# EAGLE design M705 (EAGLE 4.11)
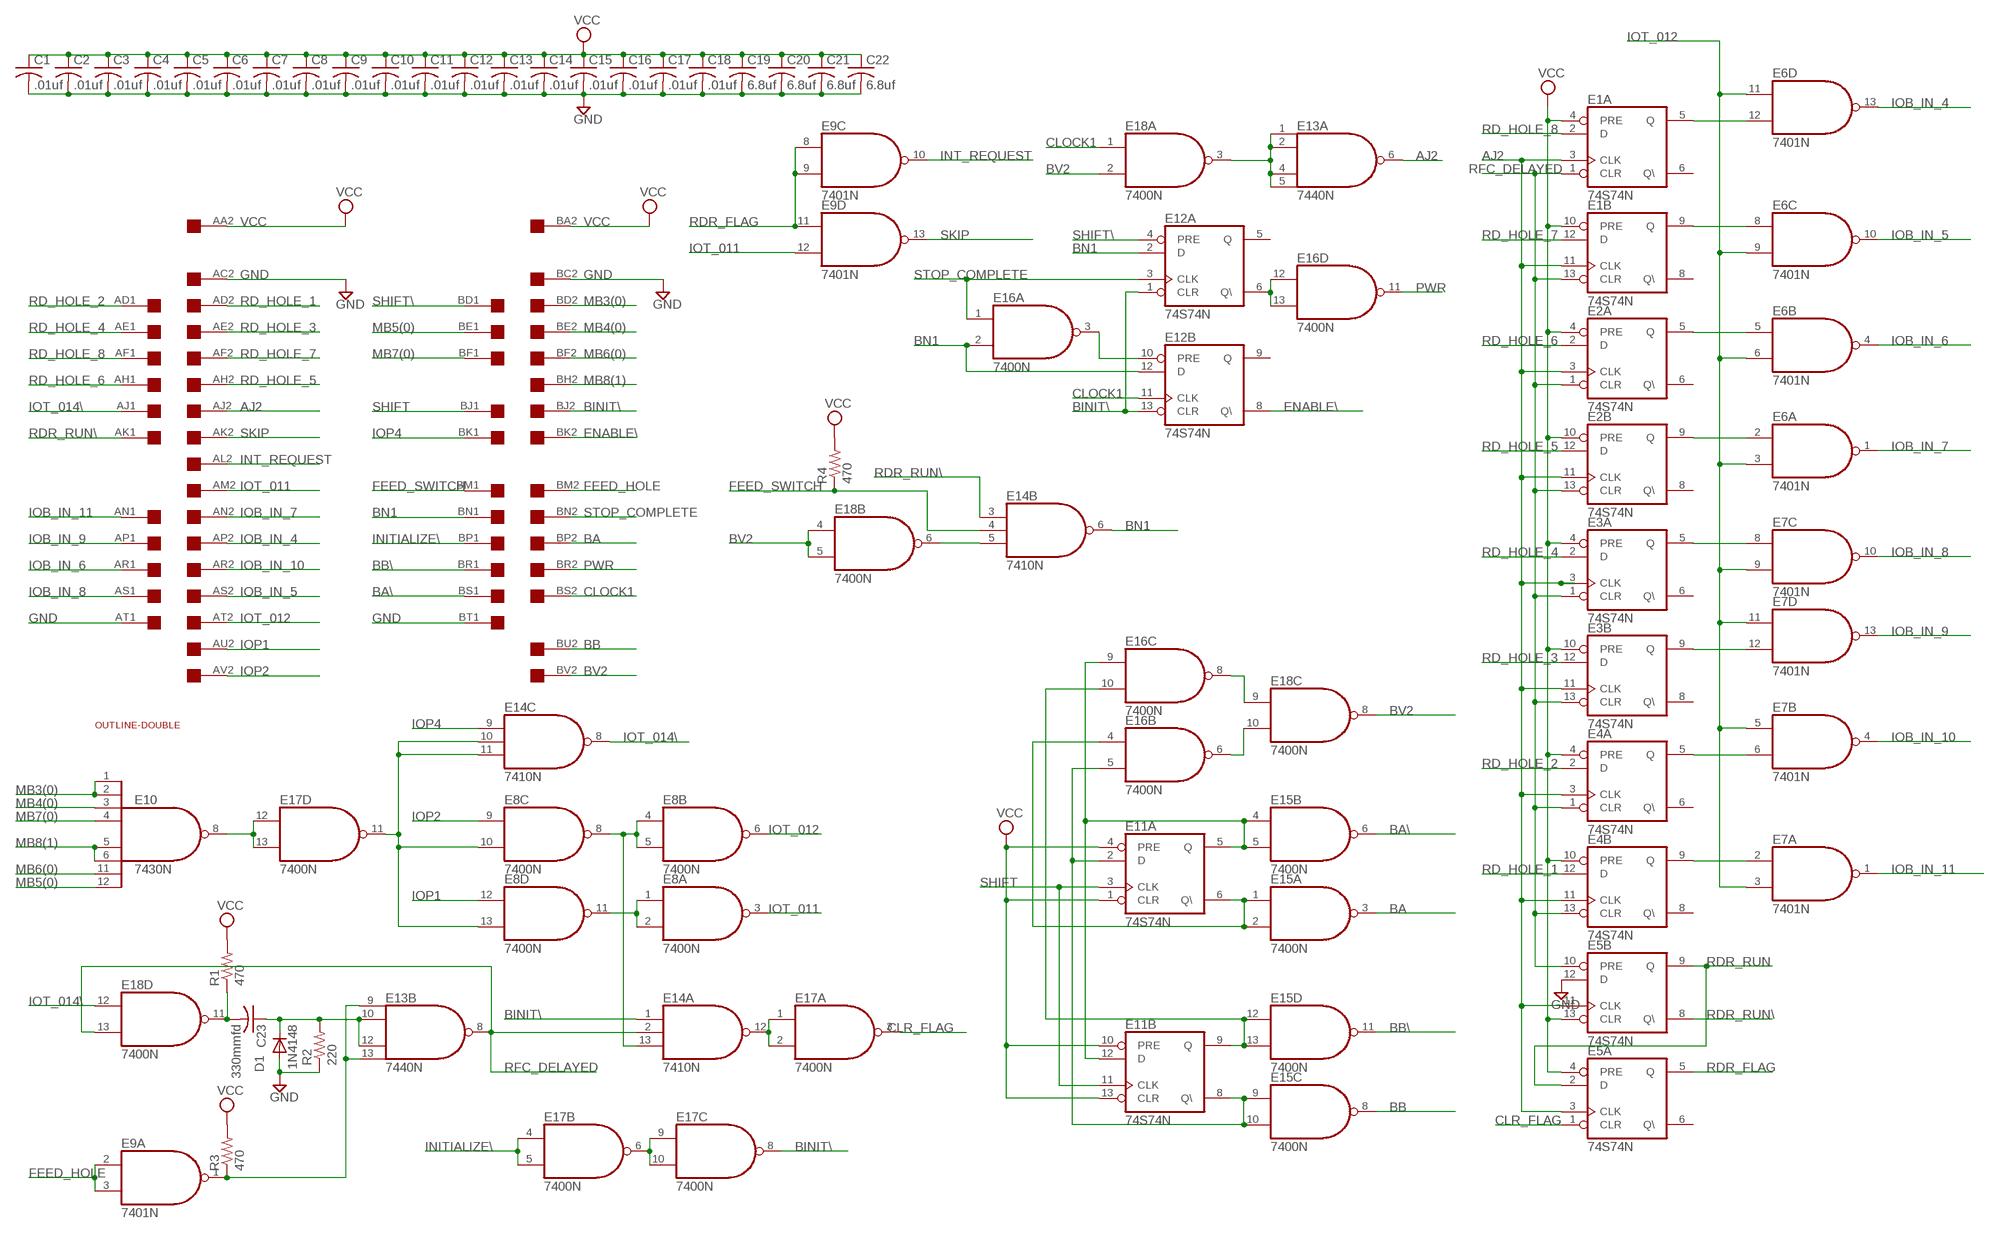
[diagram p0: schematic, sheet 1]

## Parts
C1  .01uf  C-US050-025X075  [C050-025X075]
C2  .01uf  C-US050-025X075  [C050-025X075]
C3  .01uf  C-US050-025X075  [C050-025X075]
C4  .01uf  C-US050-025X075  [C050-025X075]
C5  .01uf  C-US050-025X075  [C050-025X075]
C6  .01uf  C-US050-025X075  [C050-025X075]
C7  .01uf  C-US050-025X075  [C050-025X075]
C8  .01uf  C-US050-025X075  [C050-025X075]
C9  .01uf  C-US050-025X075  [C050-025X075]
C10  .01uf  C-US050-025X075  [C050-025X075]
C11  .01uf  C-US050-025X075  [C050-025X075]
C12  .01uf  C-US050-025X075  [C050-025X075]
C13  .01uf  C-US050-025X075  [C050-025X075]
C14  .01uf  C-US050-025X075  [C050-025X075]
C15  .01uf  C-US050-025X075  [C050-025X075]
C16  .01uf  C-US050-025X075  [C050-025X075]
C17  .01uf  C-US050-025X075  [C050-025X075]
C18  .01uf  C-US050-025X075  [C050-025X075]
C19  6.8uf  C-US150-054X183  [C150-054X183]
C20  6.8uf  C-US150-054X183  [C150-054X183]
C21  6.8uf  C-US150-054X183  [C150-054X183]
C22  6.8uf  C-US150-054X183  [C150-054X183]
C23  330mmfd  C-US050-025X075  [C050-025X075]
D1  1N4148  [DO35-10]
E1  74S74N  [DIL14]
E2  74S74N  [DIL14]
E3  74S74N  [DIL14]
E4  74S74N  [DIL14]
E5  74S74N  [DIL14]
E6  7401N  74LS01N  [DIL14]
E7  7401N  74LS01N  [DIL14]
E8  7400N  [DIL14]
E9  7401N  74LS01N  [DIL14]
E10  7430N  [DIL14]
E11  74S74N  [DIL14]
E12  74S74N  [DIL14]
E13  7440N  74S20N  [DIL14]
E14  7410N  [DIL14]
E15  7400N  [DIL14]
E16  7400N  [DIL14]
E17  7400N  [DIL14]
E18  7400N  [DIL14]
R1  470  R-US_0207/10  [0207/10]
R2  220  R-US_0207/10  [0207/10]
R3  470  R-US_0207/10  [0207/10]
R4  470  R-US_0207/10  [0207/10]
U$5  DOUBLE  [EDGE-CON4]
U$6  OUTLINE-DOUBLE  [DOUBLE]

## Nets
AJ2: E1.3(A:CLK) E1.11(B:CLK) E2.3(A:CLK) E2.11(B:CLK) E3.3(A:CLK) E3.11(B:CLK) E4.3(A:CLK) E4.11(B:CLK) E5.3(A:CLK) E5.11(B:CLK) E13.6(A:O) U$5.AJ2
BA: E15.3(A:O) U$5.BP2
BA\: E15.6(B:O) U$5.BS1
BB: E15.8(C:O) U$5.BU2
BB\: E15.11(D:O) U$5.BR1
BINIT\: E12.1(A:CLR) E12.13(B:CLR) E14.1(A:I0) E17.8(C:O) U$5.BJ2
BN1: E12.2(A:D) E12.12(B:D) E14.6(B:O) E16.2(A:I1) U$5.BN1
BV2: E18.2(A:I1) E18.4(B:I0) E18.5(B:I1) E18.8(C:O) U$5.BV2
CLOCK1: E12.11(B:CLK) E18.1(A:I0) U$5.BS2
CLR_FLAG: E5.1(A:CLR) E17.3(A:O)
ENABLE\: E12.8(B:Q\) U$5.BK2
FEED_HOLE: E9.2(A:I0) E9.3(A:I1) U$5.BM2
FEED_SWITCH: E14.4(B:I1) R4.1 U$5.BM1
GND: C1.2 C2.2 C3.2 C4.2 C5.2 C6.2 C7.2 C8.2 C9.2 C10.2 C11.2 C12.2 C13.2 C14.2 C15.2 C16.2 C17.2 C18.2 C19.2 C20.2 C21.2 C22.2 D1.A E5.12(B:D) R2.1 U$5.AC2 U$5.AT1 U$5.BC2 U$5.BT1
INITIALIZE\: E17.4(B:I0) E17.5(B:I1) U$5.BP1
INT_REQUEST: E9.10(C:O) U$5.AL2
IOB_IN_4: E6.13(D:O) U$5.AP2
IOB_IN_5: E6.10(C:O) U$5.AS2
IOB_IN_6: E6.4(B:O) U$5.AR1
IOB_IN_7: E6.1(A:O) U$5.AN2
IOB_IN_8: E7.10(C:O) U$5.AS1
IOB_IN_9: E7.13(D:O) U$5.AP1
IOB_IN_10: E7.4(B:O) U$5.AR2
IOB_IN_11: E7.1(A:O) U$5.AN1
IOP1: E8.12(D:I0) U$5.AU2
IOP2: E8.9(C:I0) U$5.AV2
IOP4: E14.9(C:I0) U$5.BK1
IOT_011: E8.3(A:O) E9.12(D:I1) U$5.AM2
IOT_012: E6.3(A:I1) E6.6(B:I1) E6.9(C:I1) E6.11(D:I0) E7.3(A:I1) E7.5(B:I0) E7.9(C:I1) E7.11(D:I0) E8.6(B:O) U$5.AT2
IOT_014\: E14.8(C:O) E18.12(D:I0) U$5.AJ1
MB3(0): E10.1(I0) E10.2(I1) U$5.BD2
MB4(0): E10.3(I2) U$5.BE2
MB5(0): E10.12(I7) U$5.BE1
MB6(0): E10.11(I6) U$5.BF2
MB7(0): E10.4(I3) U$5.BF1
MB8(1): E10.5(I4) E10.6(I5) U$5.BH2
N$2: E1.5(A:Q) E6.12(D:I1)
N$3: E1.9(B:Q) E6.8(C:I0)
N$4: E11.6(A:Q\) E15.1(A:I0) E15.2(A:I1) E16.4(B:I0)
N$5: E10.8(O) E17.12(D:I0) E17.13(D:I1)
N$6: E8.4(B:I0) E8.5(B:I1) E8.8(C:O) E14.13(A:I2)
N$7: E8.1(A:I0) E8.2(A:I1) E8.11(D:O)
N$8: E8.10(C:I1) E8.13(D:I1) E14.10(C:I1) E14.11(C:I2) E17.11(D:O)
N$9: E2.5(A:Q) E6.5(B:I0)
N$10: E2.9(B:Q) E6.2(A:I0)
N$11: E3.5(A:Q) E7.8(C:I0)
N$12: E3.9(B:Q) E7.12(D:I1)
N$13: E4.5(A:Q) E7.6(B:I1)
N$14: E4.9(B:Q) E7.2(A:I0)
N$16: E11.5(A:Q) E11.12(B:D) E15.4(B:I0) E15.5(B:I1) E16.9(C:I0)
N$17: E11.9(B:Q) E15.12(D:I0) E15.13(D:I1) E16.10(C:I1)
N$18: E11.2(A:D) E11.8(B:Q\) E15.9(C:I0) E15.10(C:I1) E16.5(B:I1)
N$19: E16.8(C:O) E18.9(C:I0)
N$20: E16.6(B:O) E18.10(C:I1)
N$21: E13.1(A:I0) E13.2(A:I1) E13.4(A:I2) E13.5(A:I3) E18.3(A:O)
N$22: E12.6(A:Q\) E16.12(D:I0) E16.13(D:I1)
N$23: E12.10(B:PRE) E16.3(A:O)
N$24: C23.2 E18.11(D:O) R1.1
N$25: C23.1 D1.C E13.10(B:I1) E13.12(B:I2) R2.2
N$26: E9.1(A:O) E13.9(B:I0) E13.13(B:I3) R3.1
N$28: E17.6(B:O) E17.9(C:I0) E17.10(C:I1)
N$29: E14.12(A:O) E17.1(A:I0) E17.2(A:I1)
N$30: E14.5(B:I2) E18.6(B:O)
PWR: E16.11(D:O) U$5.BR2
RD_HOLE_1: E4.12(B:D) U$5.AD2
RD_HOLE_2: E4.2(A:D) U$5.AD1
RD_HOLE_3: E3.12(B:D) U$5.AE2
RD_HOLE_4: E3.2(A:D) U$5.AE1
RD_HOLE_5: E2.12(B:D) U$5.AH2
RD_HOLE_6: E2.2(A:D) U$5.AH1
RD_HOLE_7: E1.12(B:D) U$5.AF2
RD_HOLE_8: E1.2(A:D) U$5.AF1
RDR_FLAG: E5.5(A:Q) E9.8(C:I0) E9.9(C:I1) E9.11(D:I0)
RDR_RUN: E5.2(A:D) E5.9(B:Q)
RDR_RUN\: E5.8(B:Q\) E14.3(B:I0) U$5.AK1
RFC_DELAYED: E1.1(A:CLR) E1.13(B:CLR) E2.1(A:CLR) E2.13(B:CLR) E3.1(A:CLR) E3.13(B:CLR) E4.1(A:CLR) E4.13(B:CLR) E5.10(B:PRE) E13.8(B:O) E14.2(A:I1) E18.13(D:I1)
SHIFT: E11.3(A:CLK) E11.11(B:CLK) U$5.BJ1
SHIFT\: E12.4(A:PRE) U$5.BD1
SKIP: E9.13(D:O) U$5.AK2
STOP_COMPLETE: E12.3(A:CLK) E16.1(A:I0) U$5.BN2
VCC: C1.1 C2.1 C3.1 C4.1 C5.1 C6.1 C7.1 C8.1 C9.1 C10.1 C11.1 C12.1 C13.1 C14.1 C15.1 C16.1 C17.1 C18.1 C19.1 C20.1 C21.1 C22.1 E1.4(A:PRE) E1.10(B:PRE) E2.4(A:PRE) E2.10(B:PRE) E3.4(A:PRE) E3.10(B:PRE) E4.4(A:PRE) E4.10(B:PRE) E5.4(A:PRE) E5.13(B:CLR) E11.1(A:CLR) E11.4(A:PRE) E11.10(B:PRE) E11.13(B:CLR) R1.2 R3.2 R4.2 U$5.AA2 U$5.BA2
Unconnected: E1.6(A:Q\) E1.8(B:Q\) E2.6(A:Q\) E2.8(B:Q\) E3.6(A:Q\) E3.8(B:Q\) E4.6(A:Q\) E4.8(B:Q\) E5.6(A:Q\) E9.4(B:O) E9.5(B:I0) E9.6(B:I1) E12.5(A:Q) E12.9(B:Q) U$5.AA1 U$5.AB1 U$5.AB2 U$5.AC1 U$5.AL1 U$5.AM1 U$5.AU1 U$5.AV1 U$5.BA1 U$5.BB1 U$5.BB2 U$5.BC1 U$5.BH1 U$5.BL1 U$5.BL2 U$5.BT2 U$5.BU1 U$5.BV1

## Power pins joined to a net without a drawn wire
GND: E1.7(P:GND) E2.7(P:GND) E3.7(P:GND) E4.7(P:GND) E5.7(P:GND) E6.7(P:GND) E7.7(P:GND) E8.7(P:GND) E9.7(P:GND) E10.7(GND) E11.7(P:GND) E12.7(P:GND) E13.7(P:GND) E14.7(P:GND) E15.7(P:GND) E16.7(P:GND) E17.7(P:GND) E18.7(P:GND)
VCC: E1.14(P:VCC) E2.14(P:VCC) E3.14(P:VCC) E4.14(P:VCC) E5.14(P:VCC) E6.14(P:VCC) E7.14(P:VCC) E8.14(P:VCC) E9.14(P:VCC) E10.14(VCC) E11.14(P:VCC) E12.14(P:VCC) E13.14(P:VCC) E14.14(P:VCC) E15.14(P:VCC) E16.14(P:VCC) E17.14(P:VCC) E18.14(P:VCC)

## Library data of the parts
C1-C23 = rcl:C-US: CAPACITOR, American symbol
D1 = diode:1N4148: DIODE
E1-E5 E11 E12 = 74xx-us:74*74: Dual D type positive edge triggered FLIP FLOP, preset and clear
E6 E7 E9 = 74xx-us:74*01: Quad 2-input NAND gate, open collector
E8 E15-E18 = 74xx-us:74*00: Quad 2-input NAND gate
E10 = 74xx-us:74*30: 8-input NAND gate
E13 = 74xx-us:74*20: Dual 4-input NAND gate
E14 = 74xx-us:74*10: Triple 3-input NAND gate
R1-R4 = rcl:R-US_: RESISTOR, American symbol
U$5 = dec-con:DOUBLE: Double-Height DEC board
U$6 = dec-con:OUTLINE-*: Board outlines for DEC boards.

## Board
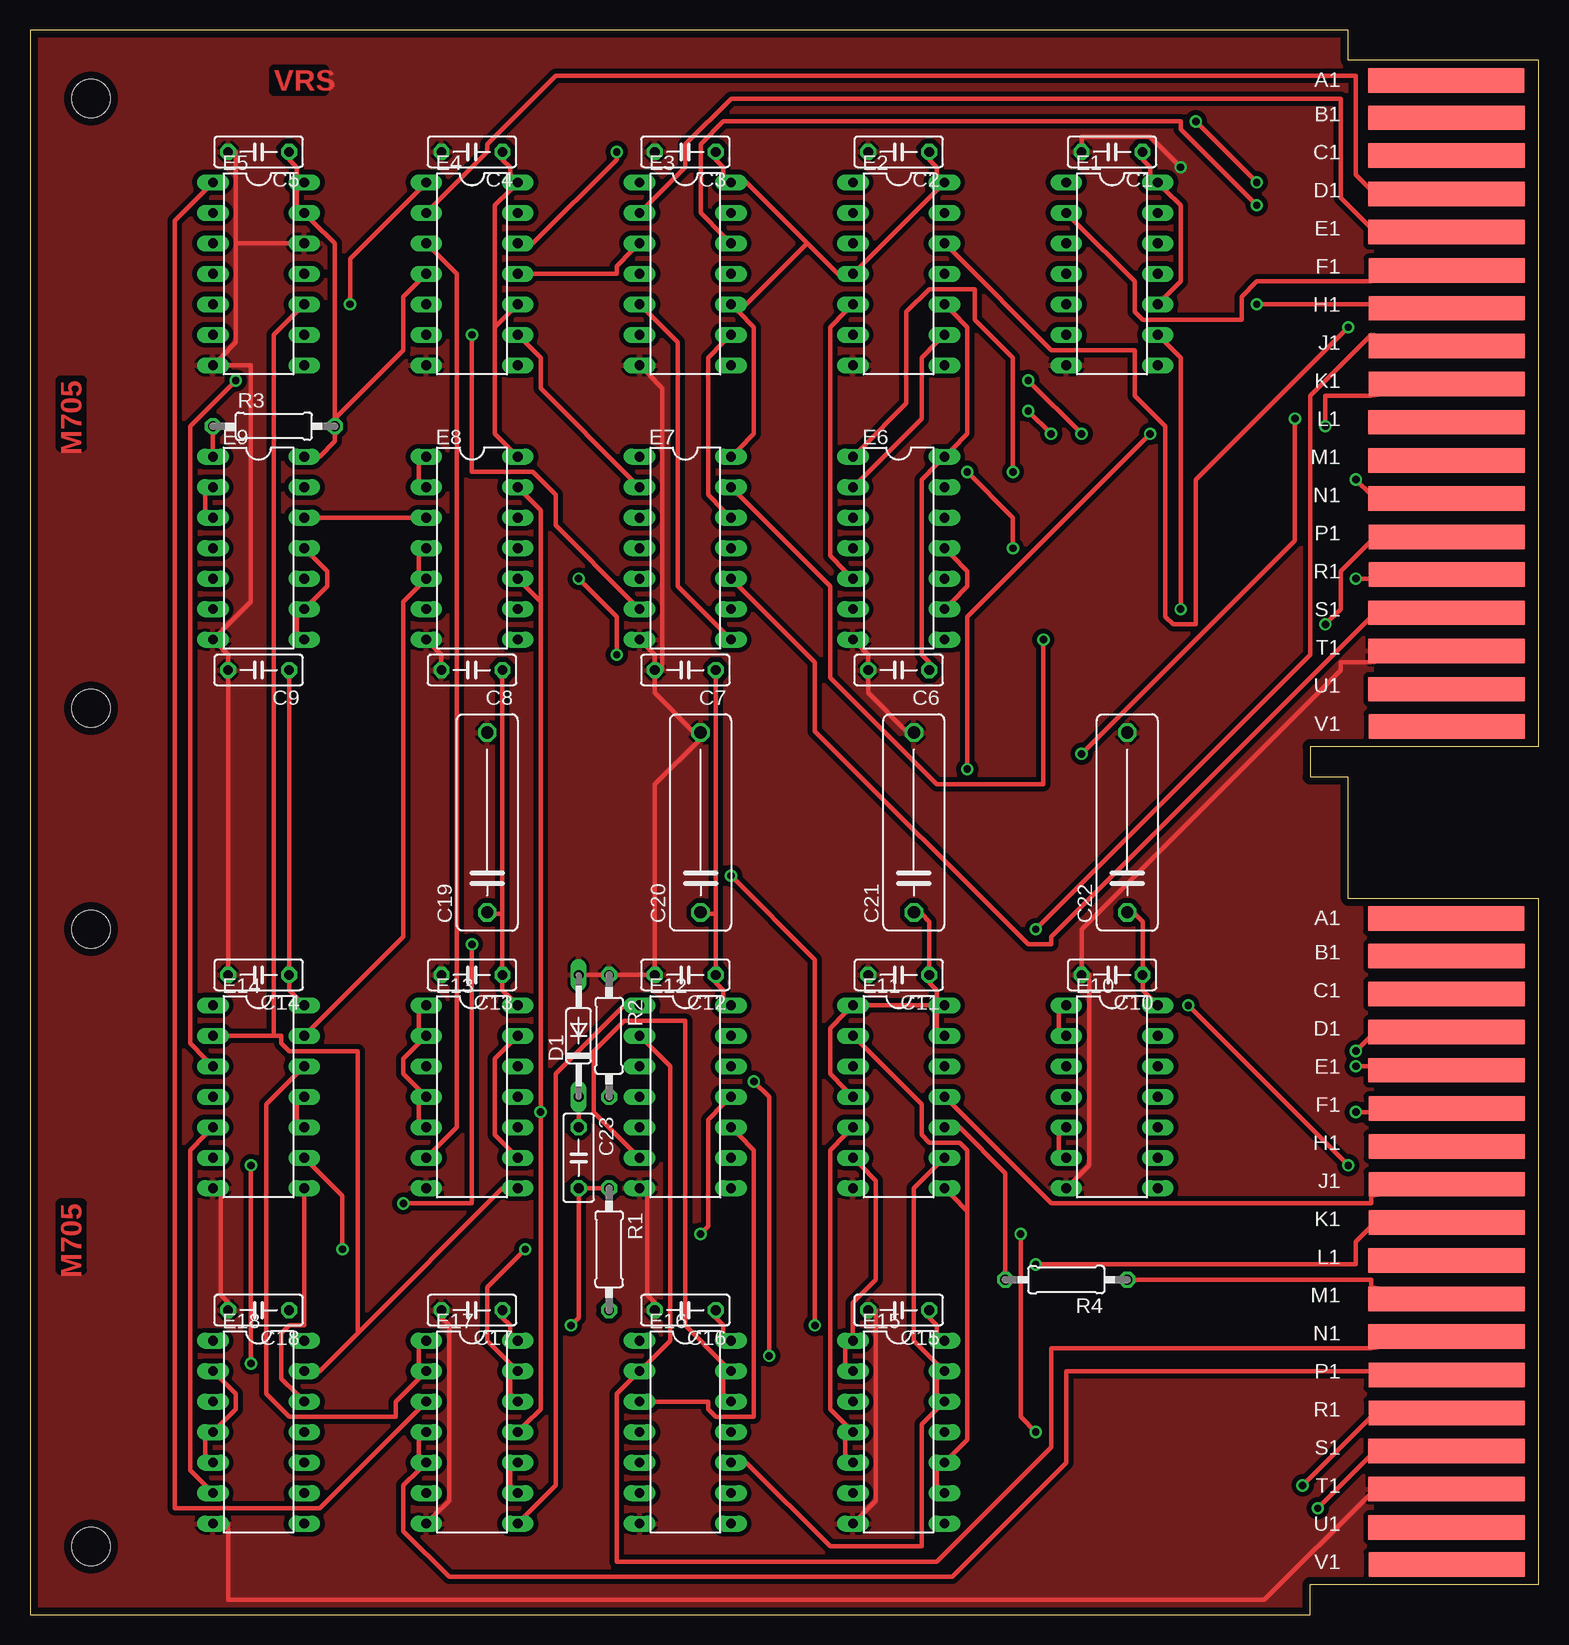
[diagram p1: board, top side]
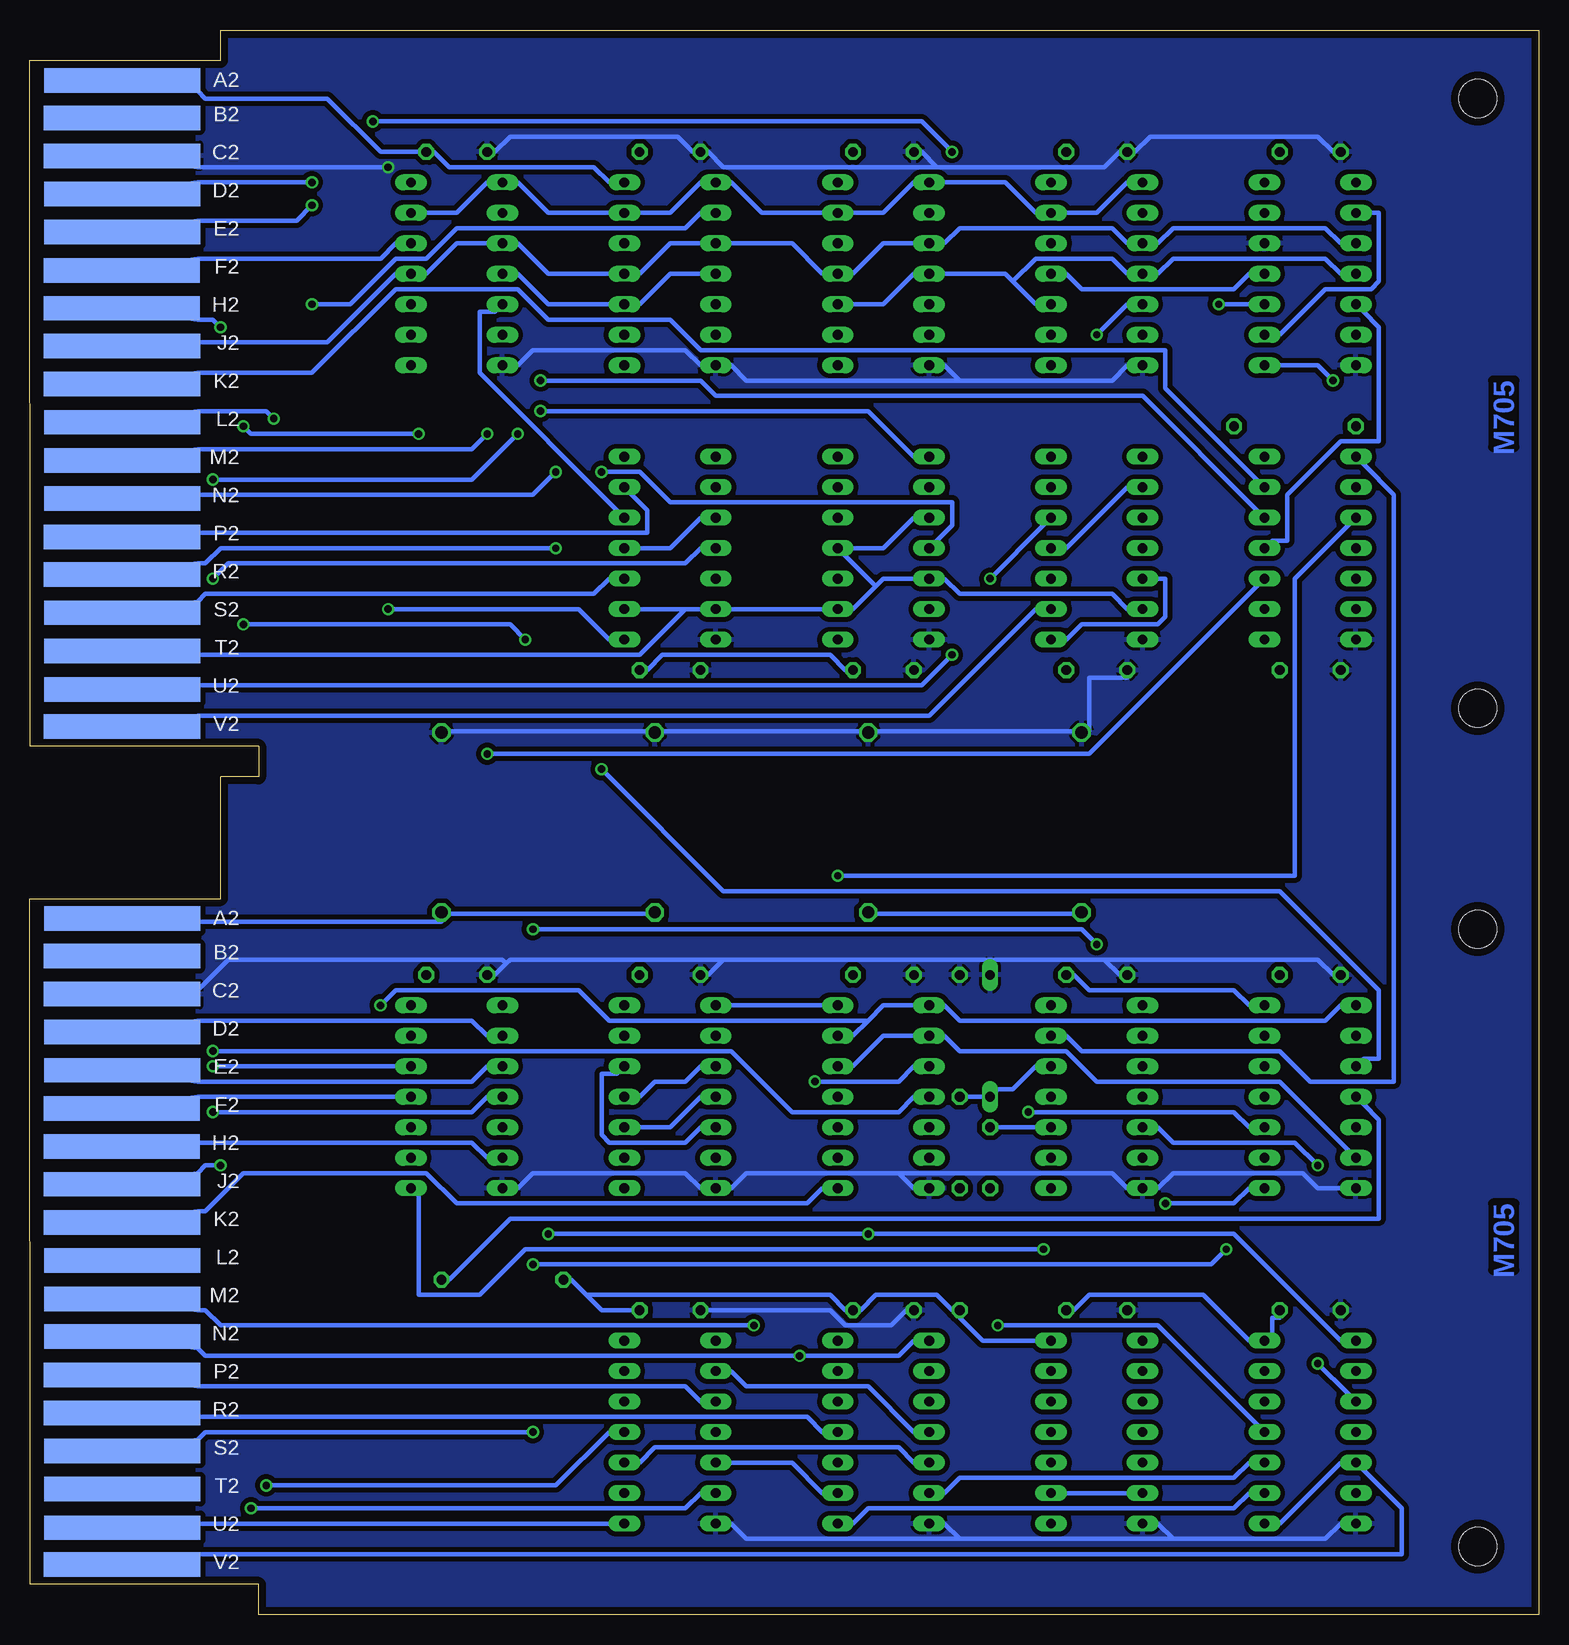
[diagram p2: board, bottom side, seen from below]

Size 125.73 x 132.08 mm. Coordinates in mm from the lower left corner, seen from the top.
Copper layers (1*16): Top 0.035mm / dielectric 1.5mm / Bottom 0.035mm
Design rules "15mils": minimum track width 15mil, minimum drill 24mil, track to track 15mil, track to pad 10mil, pad to pad 10mil, via to via 10mil, smd to smd 10mil, copper to edge 25mil, drill to drill 10mil, minimum pad ring 10mil, minimum via ring 8mil, stop-mask expansion 0mil, vias tented up to drill 0mil, thermal gap 10mil
vRestrict: area 31.8,108 to 41.9,125.7; area 49.5,108 to 59.7,125.7; area 67.3,108 to 77.5,125.7; area 85.1,108 to 95.2,125.7; area 102.9,108 to 113,125.7; area 31.8,80 to 41.9,97.8; area 49.5,80 to 59.7,97.8; area 67.3,80 to 77.5,97.8; area 85.1,80 to 95.2,97.8; area 31.8,34.3 to 41.9,52.1; area 49.5,34.3 to 59.7,52.1; area 67.3,34.3 to 77.5,52.1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

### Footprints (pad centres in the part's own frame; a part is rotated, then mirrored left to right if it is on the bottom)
C050-025X075 = drill 0.813 octagon: 1 -2.54,0; 2 2.54,0
C150-054X183 = drill 1.016 octagon: 1 -7.493,0; 2 7.493,0
DO35-10 = drill 0.813 long: A 5.08,0; C -5.08,0
DIL14 = drill 0.813 long: 1 -7.62,-3.81; 2 -5.08,-3.81; 3 -2.54,-3.81; 4 0,-3.81; 5 2.54,-3.81; 6 5.08,-3.81; 7 7.62,-3.81; 8 7.62,3.81; 9 5.08,3.81; 10 2.54,3.81; 11 0,3.81; 12 -2.54,3.81; 13 -5.08,3.81; 14 -7.62,3.81
0207/10 = drill 0.813 octagon: 1 -5.08,0; 2 5.08,0
EDGE-CON4 = smd 13.017 x 2.032: AA1 7.709,4.207; AB1 7.684,7.312; AC1 7.684,10.474; AD1 7.684,13.665; AE1 7.693,16.84; AF1 7.668,20.041; AH1 7.668,23.19; AJ1 7.668,26.34; AK1 7.668,29.515; AL1 7.693,32.69; AM1 7.693,35.89; AN1 7.693,39.04; AP1 7.668,42.24; AR1 7.668,45.39; AS1 7.693,48.565; AT1 7.693,51.74; AU1 7.693,54.94; AV1 7.668,58.026; BA1 7.709,74.057; BB1 7.684,77.162; BC1 7.684,80.324; BD1 7.684,83.515; BE1 7.693,86.69; BF1 7.668,89.891; BH1 7.668,93.04; BJ1 7.668,96.19; BK1 7.668,99.365; BL1 7.693,102.54; BM1 7.693,105.74; BN1 7.693,108.89; BP1 7.668,112.09; BR1 7.668,115.24; BS1 7.693,118.415; BT1 7.693,121.59; BU1 7.693,124.79; BV1 7.668,127.876 | smd 13.017 x 2.032 bottom: AA2 7.69,4.207; AB2 7.668,7.328; AC2 7.668,10.49; AD2 7.693,13.665; AE2 7.693,16.84; AF2 7.642,20.041; AH2 7.642,23.19; AJ2 7.668,26.34; AK2 7.668,29.515; AL2 7.693,32.69; AM2 7.693,35.89; AN2 7.693,39.04; AP2 7.668,42.24; AR2 7.668,45.39; AS2 7.693,48.565; AT2 7.693,51.74; AU2 7.693,54.966; AV2 7.668,58.026; BA2 7.69,74.057; BB2 7.668,77.178; BC2 7.668,80.34; BD2 7.693,83.515; BE2 7.693,86.69; BF2 7.642,89.891; BH2 7.642,93.04; BJ2 7.668,96.19; BK2 7.668,99.365; BL2 7.693,102.54; BM2 7.693,105.74; BN2 7.693,108.89; BP2 7.668,112.09; BR2 7.668,115.24; BS2 7.693,118.415; BT2 7.693,121.59; BU2 7.693,124.816; BV2 7.668,127.876
DOUBLE = hole 3.175: 120.65,56.515; 120.65,5.715; 120.65,74.93; 120.65,126.365

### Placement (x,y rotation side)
C1  90.17,121.92 180 top
C2  72.39,121.92 180 top
C3  54.61,121.92 180 top
C4  36.83,121.92 180 top
C5  19.05,121.92 180 top
C6  72.39,78.74 180 top
C7  54.61,78.74 180 top
C8  36.83,78.74 180 top
C9  19.05,78.74 180 top
C10  90.17,53.34 180 top
C11  72.39,53.34 180 top
C12  54.61,53.34 180 top
C13  36.83,53.34 180 top
C14  19.05,53.34 180 top
C15  72.39,25.4 180 top
C16  54.61,25.4 180 top
C17  36.83,25.4 180 top
C18  19.05,25.4 180 top
C19  38.1,66.04 90 top
C20  55.88,66.04 90 top
C21  73.66,66.04 90 top
C22  91.44,66.04 90 top
C23  45.72,38.1 270 top
D1  45.72,48.26 90 top
E1  90.17,111.76 270 top
E2  72.39,111.76 270 top
E3  54.61,111.76 270 top
E4  36.83,111.76 270 top
E5  19.05,111.76 270 top
E6  72.39,88.9 270 top
E7  54.61,88.9 270 top
E8  36.83,88.9 270 top
E9  19.05,88.9 270 top
E10  90.17,43.18 270 top
E11  72.39,43.18 270 top
E12  54.61,43.18 270 top
E13  36.83,43.18 270 top
E14  19.05,43.18 270 top
E15  72.39,15.24 270 top
E16  54.61,15.24 270 top
E17  36.83,15.24 270 top
E18  19.05,15.24 270 top
R1  48.26,30.48 270 top
R2  48.26,48.26 270 top
R3  20.32,99.06 0 top
R4  86.36,27.94 180 top
U$5  125.73,132.08 180 top
U$6  125.73,132.08 180 top

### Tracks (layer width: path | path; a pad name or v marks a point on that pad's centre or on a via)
AJ2
  Top 0.381: E13.6 33.66,38.73 35.56,40.64 35.56,111.76 33.66,113.67 E4.3 | E4.11 41.91,111.76 48.9,111.76 48.9,112.39 50.16,113.67 E3.3
  Bottom 0.381: E5.3 16.51,114.3 17.78,115.57 30.48,115.57 31.75,114.3 E4.3 34.29,114.3 35.56,115.57 48.26,115.57 49.53,114.3 E3.3 52.07,114.3 54.61,114.3 57.15,111.76 E3.11 59.69,111.76 62.23,114.3 67.31,114.3 E2.3 69.85,114.3 72.39,114.3 74.93,111.76 E2.11 77.47,111.76 82.55,111.76 85.09,114.3 E1.3 87.63,114.3 90.17,114.3 92.71,111.76 E1.11 95.25,111.76 100.97,106.05 111.76,106.05 U$5.AJ2 | E5.11 24.13,111.76 25.4,110.49 38.1,110.49 39.37,111.76 E4.11
BA
  Bottom 0.381: E15.3 69.85,17.78 71.12,19.05 111.76,19.05 U$5.BP2
BA\  (via drill 0.61)
  Top 0.381: v107.31,8.89 111.76,13.34 U$5.BS1
  Bottom 0.381: v107.31,8.89 71.12,8.89 69.85,10.16 E15.6
BB
  Bottom 0.381: E15.8 77.47,7.62 111.76,7.62 U$5.BU2
BB\  (via drill 0.61)
  Top 0.381: v106.05,10.79 111.76,16.51 U$5.BR1
  Bottom 0.381: v106.05,10.79 81.92,10.79 77.47,15.24 E15.11
BINIT\  (via drill 0.61)
  Top 0.381: E17.8 41.27,8.26 43.81,10.79 43.81,45.09 49.53,50.8 E12.1 | v96.52,50.8 v109.86,37.47
  Bottom 0.381: E14.1 16.51,50.8 17.78,49.53 48.26,49.53 49.53,50.8 E12.1 52.07,50.8 54.61,50.8 55.88,49.53 | 55.88,49.53 57.15,48.26 E12.13 | v109.86,37.47 111.12,37.47 111.76,36.83 U$5.BJ2 | v96.52,50.8 95.25,52.07 80.01,52.07 77.47,49.53 55.88,49.53
BN1
  Top 0.381: E12.2 51.44,47.62 53.34,45.72 53.34,22.86 51.44,20.95 E16.2 50.16,19.68 48.9,18.41 48.9,4.45 75.56,4.45 85.09,13.97 85.09,22.23 111.76,22.23 U$5.BN1
  Bottom 0.381: E14.6 15.88,38.73 21.59,44.45 36.83,44.45 39.37,46.99 48.26,46.99 49.53,48.26 E12.2 52.07,48.26 54.61,48.26 57.15,45.72 E12.12
BV2
  Top 0.381: E18.5 14.61,13.34 14.61,14.61 E18.4 15.88,15.88 17.14,17.14 17.14,18.41 15.88,19.68 E18.2
  Bottom 0.381: E18.8 21.59,7.62 16.51,12.7 E18.5 14.61,12.06 11.43,8.89 11.43,5.08 111.76,5.08 U$5.BV2
CLOCK1  (via drill 0.61)
  Top 0.381: v55.88,31.75 56.52,32.38 56.52,41.27 57.78,42.55 E12.11 | v83.82,15.24 82.55,16.51 v82.55,31.75
  Bottom 0.381: E18.1 16.51,22.86 25.4,31.75 v55.88,31.75 v82.55,31.75 | v83.82,15.24 111.12,15.24 111.76,14.61 U$5.BS2
CLR_FLAG
  Top 0.381: E17.3 32.38,17.14 24.13,8.89 12.06,8.89 12.06,116.2 14.61,118.75 E5.1
ENABLE\
  Bottom 0.381: E12.8 59.69,35.56 60.96,34.29 90.17,34.29 92.71,36.83 107.95,36.83 111.12,33.66 111.76,33.66 U$5.BK2
FEED_HOLE  (via drill 0.61)
  Top 0.381: E9.3 14.61,92.08 14.61,93.34 E9.2 | v58.42,61.59 65.41,54.61 v65.41,24.13
  Bottom 0.381: v58.42,61.59 20.32,61.59 20.32,86.36 15.88,90.81 E9.3 | v65.41,24.13 109.86,24.13 111.12,25.4 111.76,25.4 U$5.BM2
FEED_SWITCH
  Top 0.381: R4.1 92.08,27.94 111.76,27.94 111.76,27.3 U$5.BM1
  Bottom 0.381: E14.4 14.61,42.55 13.34,41.27 13.34,33.02 85.72,33.02 90.81,27.94 R4.1
GND  (via drill 0.61)
  Top 0.381: 17.14,114.3 17.14,121.92 C5.2 | 17.14,114.3 17.14,106.05 15.88,104.78 E5.7 16.51,104.14 18.41,104.14 18.41,84.45 15.88,81.92 E9.7 15.88,80.64 16.51,80.01 16.51,79.38 C9.2 16.51,78.11 16.51,53.98 C14.2 | 17.14,114.3 21.59,114.3 E5.12 | v95.89,120.65 93.34,123.19 87.63,123.19 87.63,122.56 C1.2 | E8.7 33.66,80.64 34.29,80.01 34.29,79.38 C8.2 | E7.7 51.44,80.64 52.07,80.01 52.07,79.38 C7.2 | C7.2 52.07,78.11 52.07,76.83 55.24,73.66 C20.2 55.88,73.03 52.07,69.22 52.07,53.98 C12.2 51.44,53.34 48.9,53.34 R2.1 47.62,53.34 46.35,53.34 D1.A | E6.7 69.22,80.64 69.85,80.01 69.85,79.38 C6.2 69.85,78.11 69.85,76.83 73.03,73.66 C21.2 | E3.7 51.44,103.5 52.7,102.23 52.7,78.74 C7.2 | E15.7 69.22,8.26 70.48,9.53 70.48,25.4 C15.2 | C17.2 34.29,24.77 34.92,24.13 34.92,9.53 33.66,8.26 E17.7 | C18.2 16.51,26.04 15.88,26.67 15.88,34.92 E14.7 | C16.2 52.07,26.04 51.44,26.67 51.44,34.92 E12.7 | E10.7 87,36.2 88.27,37.47 88.27,53.34 C10.2 87.63,53.98 87.63,57.15 109.22,78.74 109.22,79.38 111.76,79.38 U$5.AT1 | 111.76,10.16 U$5.BT1 111.76,10.16 | 111.76,10.16 111.76,10.29 | 111.76,10.16 102.87,1.27 16.51,1.27 16.51,7.62 E18.7
  Bottom 0.381: C5.2 17.14,121.92 18.41,123.19 32.38,123.19 33.66,121.92 C4.2 34.92,121.92 36.2,120.65 50.16,120.65 | 50.16,120.65 51.44,121.92 C3.2 | 50.16,120.65 67.94,120.65 69.22,121.92 C2.2 70.48,121.92 71.75,123.19 85.72,123.19 87,121.92 C1.2 | v95.89,120.65 111.76,120.65 U$5.AC2 | 48.26,102.87 35.56,102.87 34.29,104.14 E4.7 | 48.26,102.87 49.53,104.14 E3.7 | 48.26,102.87 66.04,102.87 67.31,104.14 E2.7 69.85,104.14 71.12,105.41 83.82,105.41 85.09,104.14 E1.7 | C8.2 34.29,78.11 37.47,78.11 37.47,73.66 C19.2 38.73,73.66 55.24,73.66 C20.2 56.52,73.66 73.03,73.66 C21.2 74.3,73.66 90.81,73.66 C22.2 | 30.48,6.35 17.78,6.35 16.51,7.62 E18.7 | 30.48,6.35 31.75,7.62 E17.7 | 48.26,6.35 49.53,7.62 E16.7 | 30.48,6.35 48.26,6.35 | 48.26,6.35 66.04,6.35 67.31,7.62 E15.7 | E14.7 16.51,35.56 18.41,35.56 19.68,36.83 30.48,36.83 31.75,35.56 E13.7 34.29,35.56 35.56,36.83 53.34,36.83 | 53.34,36.83 66.04,36.83 67.31,35.56 E11.7 69.85,35.56 71.12,36.83 83.82,36.83 85.09,35.56 E10.7 | 53.34,36.83 52.07,35.56 E12.7 | 36.2,54.61 34.92,53.34 C13.2 | 45.72,54.61 36.2,54.61 | 45.72,54.61 D1.A 45.72,54.61 | 67.94,54.61 69.22,53.34 C11.2 | 67.94,54.61 45.72,54.61 | 86.04,54.29 87,53.34 C10.2 | 86.04,54.29 85.72,54.61 67.94,54.61 | 36.2,54.61 18.41,54.61 17.14,53.34 C14.2 | C15.2 69.22,25.4 59.05,25.4 57.78,24.13 53.98,24.13 52.7,25.4 C16.2 | 111.76,52.07 U$5.BC2 111.76,52.07 | 111.76,52.07 111.76,51.94 | 111.76,52.07 109.22,54.61 86.36,54.61 86.04,54.29
  pour Bottom (isolate 0.406): 0,132.08 111.76,132.08 111.76,0 0,0
  pour Top (isolate 0.406): 0,132.08 111.76,132.08 111.76,0 0,0
INITIALIZE\
  Top 0.381: E17.4 32.38,14.61 32.38,13.34 E17.5 32.38,12.06 31.11,10.79 31.11,6.99 34.92,3.17 76.83,3.17 86.36,12.7 86.36,20.32 87,20.32 111.76,20.32 U$5.BP1 111.76,19.68
INT_REQUEST  (via drill 0.61)
  Top 0.381: v87.63,71.75 105.41,89.53 v105.41,99.69
  Bottom 0.381: v87.63,71.75 37.47,71.75 23.5,85.72 E9.10 | v105.41,99.69 106.05,100.33 111.76,100.33 U$5.AL2
IOB_IN_4
  Bottom 0.381: E6.13 75.56,93.34 74.3,92.08 74.3,90.17 111.76,90.17 U$5.AP2
IOB_IN_5
  Bottom 0.381: E6.10 77.47,86.36 78.74,85.09 111.12,85.09 111.76,84.45 U$5.AS2
IOB_IN_6  (via drill 0.61)
  Top 0.381: v110.49,86.36 111.76,86.36 U$5.AR1
  Bottom 0.381: v110.49,86.36 109.22,87.63 71.12,87.63 69.85,88.9 E6.4
IOB_IN_7  (via drill 0.61)
  Top 0.381: v81.92,95.25 81.92,104.78 78.74,107.95 78.74,110.49 74.93,110.49 73.03,108.58 73.03,100.97 69.22,97.16 E6.1
  Bottom 0.381: v81.92,95.25 83.82,93.34 111.76,93.34 U$5.AN2
IOB_IN_8
  Top 0.381: E7.10 59.05,85.72 65.41,79.38 65.41,73.66 83.19,55.88 85.09,55.88 85.09,56.52 111.76,83.19 U$5.AS1
IOB_IN_9  (via drill 0.61)
  Top 0.381: v84.45,81.28 84.45,69.22 75.56,69.22 66.67,78.11 66.67,85.72 59.05,93.34 E7.13 | v107.95,82.55 109.22,83.82 109.22,87 111.76,89.53 U$5.AP1
  Bottom 0.381: v84.45,81.28 85.72,82.55 v107.95,82.55
IOB_IN_10  (via drill 0.61)
  Top 0.381: v78.11,95.25 81.92,91.44 v81.92,88.9
  Bottom 0.381: v78.11,95.25 74.93,95.25 72.39,92.71 48.9,92.71 48.9,90.81 50.16,89.53 E7.4 | v81.92,88.9 109.86,88.9 111.12,87.63 111.76,87.63 U$5.AR2
IOB_IN_11  (via drill 0.61)
  Top 0.381: v83.19,100.33 v85.09,98.42 | v110.49,94.61 111.76,93.34 U$5.AN1
  Bottom 0.381: v83.19,100.33 55.88,100.33 52.07,96.52 E7.1 | v85.09,98.42 88.9,94.61 v110.49,94.61
IOP1  (via drill 0.61)
  Top 0.381: v45.72,86.36 48.9,83.19 v48.9,80.01
  Bottom 0.381: v45.72,86.36 41.27,90.81 E8.12 | v48.9,80.01 51.44,77.47 111.76,77.47 U$5.AU2
IOP2
  Bottom 0.381: E8.9 41.91,83.82 50.8,74.93 111.76,74.93 U$5.AV2
IOP4  (via drill 0.61)
  Top 0.381: v26.04,30.48 26.04,34.92 23.5,37.47 E14.9 | v83.82,29.21 110.49,29.21 110.49,31.11 111.76,32.38 U$5.BK1
  Bottom 0.381: v26.04,30.48 27.3,29.21 v83.82,29.21
IOT_011  (via drill 0.61)
  Top 0.381: E9.12 24.13,91.44 31.75,91.44 E8.3 | v83.19,102.87 v87.63,98.42
  Bottom 0.381: v83.19,102.87 69.85,102.87 68.58,101.6 33.02,101.6 23.5,92.08 E9.12 | v87.63,98.42 88.9,97.16 111.76,97.16 U$5.AM2
IOT_012
  Top 0.381: E6.11 76.83,88.27 78.11,87 78.11,85.72 76.83,84.45 E6.9
  Bottom 0.381: 71.12,83.82 74.93,83.82 E6.9 | 71.12,83.82 69.85,83.82 E6.6 67.31,83.82 59.69,83.82 E7.9 57.15,83.82 55.24,85.72 | E6.3 69.85,91.44 72.39,88.9 74.93,88.9 E6.11 | E8.6 34.29,83.82 35.56,85.09 48.26,85.09 49.53,86.36 E7.5 52.07,86.36 54.61,86.36 55.24,85.72 | 55.24,85.72 57.78,88.27 E7.11 57.15,88.9 54.61,88.9 52.07,91.44 E7.3 | 71.12,83.82 74.93,80.01 111.76,80.01 U$5.AT2
IOT_014\  (via drill 0.61)
  Top 0.381: E18.12 22.23,18.41 20.95,19.68 20.95,23.5 21.59,24.13 22.86,24.13 22.86,34.92 E14.8 | v31.11,34.29 36.83,34.29 v36.83,55.88 | v83.82,57.15 106.68,80.01 106.68,101.6 111.76,106.68 U$5.AJ1
  Bottom 0.381: v31.11,34.29 25.4,34.29 24.13,35.56 E14.8 | v36.83,55.88 38.1,57.15 v83.82,57.15
MB3(0)
  Top 0.381: E10.2 85.72,48.9 85.72,50.16 E10.1
  Bottom 0.381: E10.2 87.63,48.26 88.9,49.53 111.76,49.53 U$5.BD2
MB4(0)
  Bottom 0.381: E10.3 87.63,45.72 88.9,44.45 111.76,44.45 U$5.BE2
MB5(0)  (via drill 0.61)
  Top 0.381: v110.49,45.72 111.76,45.72 U$5.BE1
  Bottom 0.381: v110.49,45.72 95.25,45.72 E10.12
MB6(0)
  Bottom 0.381: E10.11 95.25,43.18 111.76,43.18 U$5.BF2
MB7(0)  (via drill 0.61)
  Top 0.381: v110.49,41.91 111.76,41.91 U$5.BF1
  Bottom 0.381: v110.49,41.91 88.9,41.91 87.63,43.18 E10.4
MB8(1)
  Top 0.381: E10.6 85.72,38.73 85.72,40.01 E10.5
  Bottom 0.381: E10.6 87.63,38.1 88.9,39.37 111.76,39.37 U$5.BH2
N$2
  Bottom 0.381: E6.12 76.83,92.08 88.27,103.5 88.27,108.58 87,108.58 E1.5
N$3  (via drill 0.61)
  Top 0.381: v95.89,83.82 95.89,104.78 94.61,106.05 E1.9
  Bottom 0.381: v95.89,83.82 80.01,83.82 77.47,81.28 E6.8
N$4
  Top 0.381: E15.2 67.94,20.95 67.94,22.23 E15.1 68.58,23.5 68.58,26.04 70.48,27.94 70.48,36.2 69.22,37.47 E11.6
  Bottom 0.381: E16.4 52.07,15.24 55.88,19.05 66.04,19.05 67.31,20.32 E15.2
N$5  (via drill 0.61)
  Top 0.381: E17.12 40.01,18.41 40.01,19.68 E17.13 40.01,20.95 38.1,22.86 38.1,27.3 v41.27,30.48
  Bottom 0.381: v41.27,30.48 84.45,30.48 88.27,26.67 93.34,26.67 93.34,34.92 E10.8
N$6
  Top 0.381: E14.13 23.5,48.9 31.11,56.52 31.11,84.45 32.38,85.72 E8.5 32.38,87 32.38,88.27 E8.4
  Bottom 0.381: E8.8 39.37,81.28 38.1,82.55 31.75,82.55 31.11,83.19 31.11,86.36 31.75,86.36 E8.5
N$7
  Top 0.381: E8.2 32.38,94.61 32.38,95.89 E8.1
  Bottom 0.381: E8.11 39.37,88.9 34.29,93.98 E8.2
N$8  (via drill 0.61)
  Top 0.381: E14.10 22.23,41.27 22.23,42.55 E14.11 | 42.55,84.45 v42.55,41.91 42.55,17.14 41.27,15.88 E17.11 | 42.55,84.45 41.27,85.72 E8.10 | 42.55,84.45 42.55,92.08 41.27,93.34 E8.13
  Bottom 0.381: v42.55,41.91 25.4,41.91 24.13,40.64 E14.10
N$9
  Top 0.381: E6.5 67.94,87 66.67,88.27 66.67,107.31 67.94,108.58 E2.5
N$10
  Top 0.381: E6.2 69.22,94.61 74.3,99.69 74.3,104.78 75.56,106.05 E2.9
N$11
  Top 0.381: E7.8 57.78,81.92 53.98,85.72 53.98,106.05 51.44,108.58 E3.5
N$12
  Top 0.381: E7.12 57.78,92.08 56.52,93.34 56.52,104.78 57.78,106.05 E3.9
N$13  (via drill 0.61)
  Top 0.381: v36.83,106.68 36.83,95.25 41.91,95.25 43.81,93.34 43.81,90.81 50.16,84.45 E7.6
  Bottom 0.381: v36.83,106.68 34.29,109.22 E4.5
N$14
  Top 0.381: E7.2 50.16,94.61 42.55,102.23 42.55,104.78 41.27,106.05 E4.9
N$16
  Top 0.381: E15.5 67.94,13.34 67.94,14.61 E15.4 67.94,15.88 66.67,17.14 66.67,38.73 67.94,40.01 E11.5
  Bottom 0.381: E11.5 69.85,40.64 71.12,39.37 77.47,39.37 78.11,40.01 78.11,45.09 76.83,45.09 E11.12 | E16.9 59.69,10.16 62.23,12.7 67.31,12.7 E15.5
N$17
  Top 0.381: E16.10 59.69,12.7 66.67,5.71 74.3,5.71 74.3,15.88 75.56,17.14 E15.12 75.56,18.41 75.56,19.68 E15.13 75.56,20.95 73.66,22.86 73.66,35.56 75.56,37.47 E11.9
N$18
  Top 0.381: E15.9 75.56,10.79 75.56,12.06 E15.10 76.83,13.34 78.11,14.61 78.11,33.66 | 78.11,33.66 76.83,34.92 E11.8 | 78.11,33.66 78.11,38.73 77.47,39.37 74.93,39.37 74.3,40.01 74.3,42.55 69.22,47.62 E11.2
  Bottom 0.381: E16.5 52.07,12.7 53.34,13.97 73.66,13.97 74.93,12.7 E15.10
N$19
  Bottom 0.381: E18.9 24.13,10.16 25.4,8.89 55.88,8.89 57.15,7.62 E16.8
N$20
  Bottom 0.381: E18.10 24.13,12.7 25.4,11.43 48.26,11.43 49.53,10.16 E16.6
N$21  (via drill 0.61)
  Top 0.381: E13.1 32.38,50.16 32.38,48.9 E13.2 32.38,47.62 31.11,46.35 31.11,45.09 32.38,43.81 E13.4 32.38,42.55 32.38,41.27 E13.5 | v18.41,20.95 v18.41,37.47
  Bottom 0.381: v18.41,20.95 15.88,18.41 E18.3 | v18.41,37.47 20.32,39.37 30.48,39.37 31.75,40.64 E13.5
N$22
  Top 0.381: E16.12 57.78,18.41 57.78,19.68 E16.13 57.78,20.95 54.61,24.13 54.61,49.53 49.53,49.53 46.99,46.99 46.99,41.91 50.16,38.73 E12.6
N$23
  Top 0.381: E16.3 52.07,17.78 56.52,17.78 56.52,17.14 57.15,16.51 60.33,16.51 60.33,38.73 59.05,40.01 E12.10
N$24  (via drill 0.61)
  Top 0.381: v45.09,24.13 45.72,24.77 45.72,34.92 C23.2 46.35,35.56 47.62,35.56 R1.1
  Bottom 0.381: v45.09,24.13 31.75,24.13 23.5,15.88 E18.11
N$25
  Top 0.381: C23.1 45.72,41.27 45.72,41.91 D1.C
  Bottom 0.381: E13.10 41.91,40.64 45.09,40.64 C23.1 | E13.12 41.91,45.72 43.81,43.81 45.09,43.81 D1.C 46.35,43.18 47.62,43.18 R2.2
N$26
  Top 0.381: E9.1 15.24,97.16 15.24,98.42 R3.1 | E13.9 40.01,38.73 38.73,40.01 38.73,46.35 40.01,47.62 E13.13
  Bottom 0.381: E9.1 14.61,95.89 12.06,93.34 12.06,44.45 19.05,44.45 21.59,46.99 38.1,46.99 39.37,48.26 E13.13
N$28
  Top 0.381: E17.10 40.01,12.06 40.01,10.79 E17.9
  Bottom 0.381: E17.6 34.29,10.16 39.37,10.16 E17.9
N$29
  Top 0.381: E17.1 32.38,22.23 32.38,20.95 E17.2 32.38,19.68 30.48,17.78 30.48,16.51 21.59,16.51 19.68,18.41 19.68,42.55 22.23,45.09 E14.12
N$30
  Top 0.381: E18.6 14.61,10.79 13.34,12.06 13.34,38.73 14.61,40.01 E14.5
PWR
  Bottom 0.381: E16.11 59.69,15.24 60.96,16.51 111.76,16.51 U$5.BR2
RD_HOLE_1  (via drill 0.61)
  Top 0.381: v48.9,121.92 48.9,121.28 41.91,114.3 E4.12 | v97.16,124.46 v102.23,119.38
  Bottom 0.381: v48.9,121.92 51.44,124.46 v97.16,124.46 | v102.23,119.38 111.76,119.38 U$5.AD2
RD_HOLE_2
  Top 0.381: E4.2 33.66,117.47 38.1,121.92 38.1,122.56 43.81,128.27 110.49,128.27 110.49,120.02 111.76,118.75 U$5.AD1
RD_HOLE_3  (via drill 0.61)
  Top 0.381: v102.23,117.47 95.89,123.83 95.89,124.46 57.78,124.46 55.88,122.56 55.88,116.84 57.78,114.94 E3.12
  Bottom 0.381: v102.23,117.47 103.5,116.2 111.76,116.2 U$5.AE2
RD_HOLE_4
  Top 0.381: E3.2 51.44,117.47 54.61,120.65 54.61,122.56 58.42,126.36 109.22,126.36 109.22,118.11 111.76,115.57 U$5.AE1
RD_HOLE_5  (via drill 0.61)
  Top 0.381: v109.86,107.31 97.16,94.61 97.16,82.55 95.25,82.55 94.61,83.19 94.61,99.06 92.08,101.6 92.08,105.41 85.09,105.41 76.83,113.67 E2.12
  Bottom 0.381: v109.86,107.31 110.49,107.95 111.76,107.95 U$5.AH2
RD_HOLE_6  (via drill 0.61)
  Top 0.381: v102.23,109.22 111.76,109.22 U$5.AH1
  Bottom 0.381: v102.23,109.22 99.06,109.22 95.25,113.03 92.71,113.03 90.17,115.57 71.12,115.57 69.85,116.84 E2.2
RD_HOLE_7
  Bottom 0.381: E1.12 95.25,114.3 96.52,113.03 111.76,113.03 U$5.AF2
RD_HOLE_8
  Top 0.381: E1.2 87,116.2 92.08,111.12 92.08,108.58 92.71,107.95 100.97,107.95 100.97,109.86 102.23,111.12 111.76,111.12 U$5.AF1
RDR_FLAG
  Top 0.381: E9.8 22.23,81.92 22.23,83.19 E9.9 23.5,84.45 24.77,85.72 24.77,87 23.5,88.27 E9.11
  Bottom 0.381: E5.5 14.61,108.58 13.34,107.31 13.34,97.79 16.51,97.79 20.95,93.34 20.95,89.53 22.23,89.53 E9.11
RDR_RUN
  Bottom 0.381: E5.9 21.59,106.68 17.78,110.49 13.97,110.49 13.34,111.12 13.34,116.84 13.97,116.84 E5.2
RDR_RUN\  (via drill 0.61)
  Top 0.381: v17.14,102.87 13.34,99.06 13.34,47.62 14.61,46.35 E14.3 | v107.95,99.06 107.95,101.6 111.76,101.6 U$5.AK1 | v93.34,98.42 78.11,83.19 v78.11,70.48
  Bottom 0.381: v17.14,102.87 18.41,104.14 21.59,104.14 E5.8 | v107.95,99.06 107.31,98.42 v93.34,98.42 | v78.11,70.48 67.94,60.33 21.59,60.33 13.34,52.07 13.34,46.35 14.61,46.35 E14.3
RFC_DELAYED  (via drill 0.61)
  Top 0.381: 27.3,23.5 39.37,35.56 E13.8 | 27.3,23.5 24.13,20.32 E18.13 | 20.32,48.26 20.95,48.26 20.95,47.62 21.59,46.99 27.3,46.99 27.3,23.5 | 20.32,48.26 16.51,48.26 E14.2 | 20.32,48.26 20.32,106.68 22.23,108.58 E5.10 | v26.67,109.22 26.67,113.03 32.38,118.75 E4.1
  Bottom 0.381: E1.13 92.71,116.84 90.17,116.84 87.63,119.38 E1.1 85.09,119.38 82.55,116.84 77.47,116.84 E2.13 74.93,116.84 72.39,116.84 69.85,119.38 E2.1 67.31,119.38 64.77,116.84 59.69,116.84 E3.13 57.15,116.84 54.61,116.84 52.07,119.38 E3.1 49.53,119.38 44.45,119.38 41.91,116.84 E4.13 39.37,116.84 36.83,116.84 34.29,119.38 E4.1 | v26.67,109.22 24.13,109.22 E5.10
SHIFT
  Top 0.381: E11.11 76.83,42.55 85.09,34.29 111.76,34.29 111.76,34.92 U$5.BJ1
  Bottom 0.381: E11.3 69.85,45.72 71.12,44.45 73.66,44.45 74.93,43.18 E11.11
SHIFT\  (via drill 0.61)
  Top 0.381: v110.49,46.99 111.76,48.26 U$5.BD1
  Bottom 0.381: v110.49,46.99 67.31,46.99 62.23,41.91 53.34,41.91 52.07,43.18 E12.4
SKIP
  Bottom 0.381: E9.13 23.5,94.61 31.11,102.23 31.11,105.41 69.85,105.41 72.39,107.95 82.55,107.95 85.09,110.49 95.25,110.49 102.23,103.5 111.76,103.5 U$5.AK2
STOP_COMPLETE  (via drill 0.61)
  Top 0.381: v60.33,44.45 61.59,43.18 v61.59,21.59
  Bottom 0.381: E16.1 52.07,22.86 53.34,21.59 v61.59,21.59 111.12,21.59 111.76,22.23 U$5.BN2 | v60.33,44.45 53.34,44.45 52.07,45.72 E12.3
VCC
  Top 0.381: E14.14 22.23,51.44 21.59,52.07 21.59,52.7 C14.1 21.59,53.98 21.59,78.11 C9.1 | E13.14 40.01,51.44 39.37,52.07 39.37,52.7 C13.1 39.37,53.98 39.37,58.42 | 39.37,58.42 39.37,78.11 C8.1 | 39.37,58.42 38.73,58.42 C19.1 | C16.1 57.15,24.77 57.78,24.13 57.78,23.5 E16.14 | C17.1 39.37,24.77 40.01,24.13 40.01,23.5 E17.14 | C15.1 74.93,24.77 75.56,24.13 75.56,23.5 E15.14 | E11.10 77.47,40.64 81.28,36.83 81.28,28.57 R4.2 | E12.14 57.78,51.44 57.78,52.07 57.15,52.7 C12.1 57.15,53.98 57.15,58.42 | 57.15,58.42 57.15,78.11 C7.1 | 57.15,58.42 56.52,58.42 C20.1 | E10.14 93.34,51.44 92.71,52.07 92.71,52.7 C10.1 92.71,53.98 92.71,57.78 92.08,58.42 C22.1 | E11.14 74.93,50.8 69.85,50.8 E11.1 67.94,50.16 66.67,48.9 66.67,45.09 67.94,43.81 E11.4 | E11.14 75.56,51.44 75.56,52.07 74.93,52.7 C11.1 74.93,53.98 74.93,57.78 74.3,58.42 C21.1 | E11.13 75.56,48.9 75.56,50.16 E11.14 | C5.1 21.59,121.28 22.23,120.65 22.23,120.02 E5.14 22.23,118.75 22.23,117.47 E5.13 23.5,116.2 25.4,114.3 25.4,99.69 | E9.14 24.13,96.52 25.4,97.79 25.4,98.42 R3.2 | 25.4,99.69 31.11,105.41 31.11,109.86 32.38,111.12 E4.4 | 25.4,99.69 R3.2 | 25.4,99.69 R3.2 | C4.1 39.37,121.28 40.01,120.65 40.01,120.02 E4.14 40.01,118.75 38.73,117.47 38.73,107.31 | 38.73,107.31 38.73,98.42 40.01,97.16 E8.14 | 38.73,107.31 40.01,108.58 E4.10 | E7.14 59.05,97.16 60.33,98.42 60.33,107.31 59.05,108.58 E3.10 59.69,109.22 64.77,114.3 | C6.1 74.93,79.38 74.3,80.01 74.3,94.61 75.56,95.89 E6.14 76.83,97.16 78.11,98.42 78.11,107.31 76.83,108.58 E2.10 | E1.10 94.61,109.86 95.89,111.12 95.89,117.47 94.61,118.75 E1.14 93.34,120.02 93.34,120.65 92.71,121.28 C1.1
  Top 0.381: C2.1 74.93,121.28 75.56,120.65 75.56,120.02 E2.14 75.56,118.75 69.22,112.39 E2.4 67.31,111.76 64.77,114.3 | C3.1 57.15,121.28 57.78,120.65 57.78,120.02 E3.14 59.69,119.38 64.77,114.3
  Bottom 0.381: E14.14 24.13,50.8 25.4,52.07 37.47,52.07 38.73,53.34 C13.1 | C18.1 21.59,24.77 22.23,24.77 22.23,23.5 E18.14 24.13,22.86 27.94,26.67 37.47,26.67 38.73,25.4 C17.1 | E17.14 41.91,22.86 46.35,22.86 48.26,24.77 R1.2 48.9,25.4 50.16,26.67 55.24,26.67 56.52,25.4 C16.1 57.78,25.4 59.05,26.67 79.38,26.67 | E11.4 69.85,43.18 72.39,40.64 74.93,40.64 E11.10 | 79.38,26.67 78.11,25.4 75.56,25.4 C15.1 | 79.38,26.67 80.64,27.94 R4.2 | 90.81,58.42 74.3,58.42 C21.1 | 90.81,58.42 C22.1 90.81,58.42 | E12.14 59.69,50.8 67.31,50.8 E11.1 | C19.1 38.73,58.42 55.24,58.42 C20.1 | E5.4 16.51,111.76 17.78,113.03 30.48,113.03 31.75,111.76 E4.4 34.29,111.76 35.56,113.03 41.91,113.03 43.81,111.12 | E3.10 57.15,109.22 54.61,109.22 52.07,111.76 E3.4 49.53,111.76 44.45,111.76 43.81,111.12 | E2.4 69.85,111.76 72.39,111.76 74.93,109.22 E2.10 77.47,109.22 82.55,109.22 85.09,111.76 E1.4 | E2.14 77.47,119.38 78.74,120.65 90.81,120.65 92.08,121.92 C1.1 93.34,121.92 96.52,121.92 100.97,126.36 111.12,126.36 111.76,127 U$5.AA2 | 43.81,111.12 41.91,109.22 E4.10 | C7.1 57.78,78.74 59.05,80.01 73.03,80.01 74.3,78.74 C6.1 | 90.81,58.42 91.44,57.78 111.76,57.78 U$5.BA2

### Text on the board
Top: VRS | M705 | M705
Bottom: M705 | M705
